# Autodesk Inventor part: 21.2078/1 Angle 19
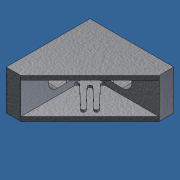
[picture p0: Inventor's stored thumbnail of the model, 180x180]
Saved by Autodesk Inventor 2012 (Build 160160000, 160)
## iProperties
Created: 2012-10
Part Number: 21.2078/1 Angle 19
Document SubType Name: Modeling
Designer: Administrator
Density: 2.71 g/cm^3
Material: Aluminum-6061
Mass: 27.2255 g
Surface Area: 63.7712 cm^2
Volume: 10.0463 cm^3
Description: Angle 19 GD-Z
Author: Administrator
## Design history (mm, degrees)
feature "Base1"
body "Solid1"
